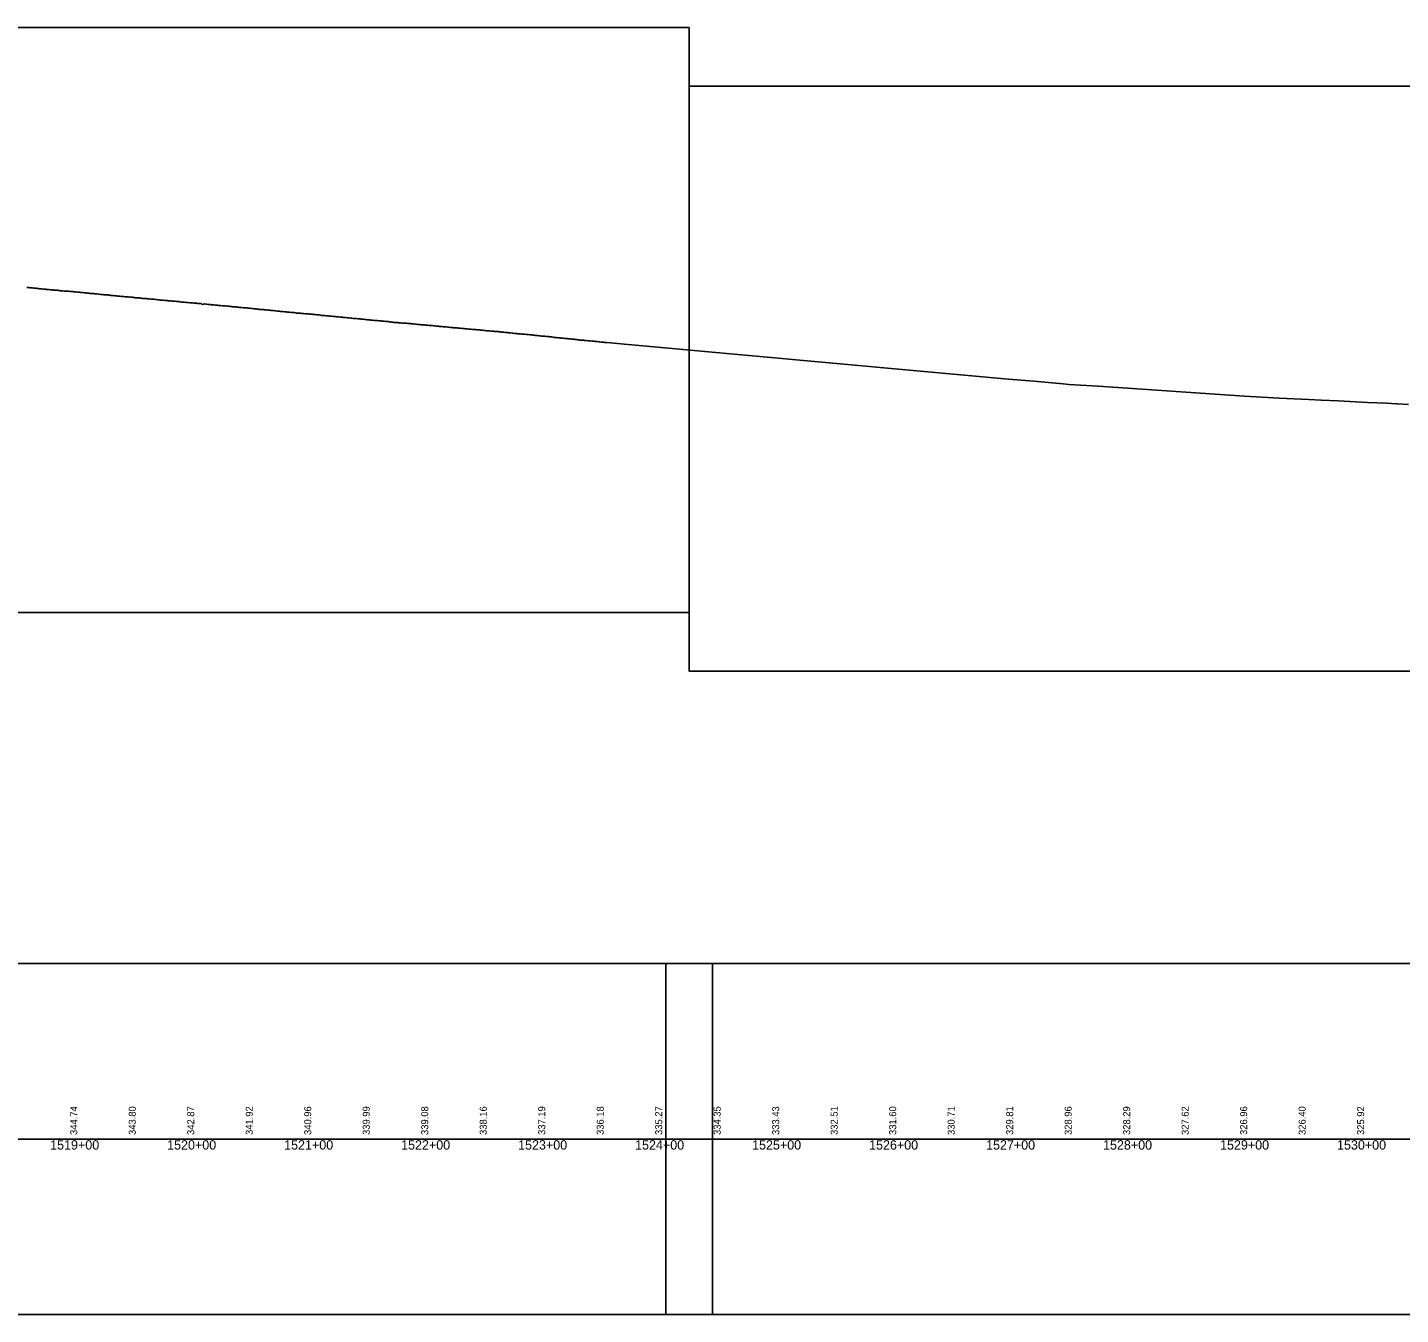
# Model space of a CAD drawing. Extents: x 2898 to 49495, y -15038 to -13538.
# Drawn here: x 41410 to 42583, y -15038 to -13938 of the extents above; entities that cross this region are included whole.
import ezdxf

# ---------------------------------------------------------------- set-up
doc = ezdxf.new("R2010")
doc.units = 0
for name, color, linetype in [('RD_DDB_Profile_EX', 7, 'Continuous'), ('RD_DDB_StaTX', 7, 'Continuous'), ('RD_DDB_StripGrade', 7, 'Continuous'), ('RD_GPK_Profile_Cell', 7, 'Continuous'), ('RD_SHT_ShtClip', 7, 'Continuous')]:
    doc.layers.add(name, color=color, linetype=linetype)

msp = doc.modelspace()

# ---------------------------------------------------------------- linework, layer by layer
at = {"layer": 'RD_DDB_Profile_EX'}
for points in [[(41409.2, -14160.7), (41410.2, -14160.8), (41411.2, -14160.8), (41412.2, -14160.9), (41413.2, -14161), (41414.2, -14161.1), (41415.2, -14161.2), (41416.2, -14161.3), (41417.2, -14161.4)], [(41417.2, -14161.4), (41418.2, -14161.6), (41419.2, -14161.7), (41420.2, -14161.8), (41421.2, -14161.9), (41422.2, -14161.9), (41423.2, -14162), (41424.2, -14162.1), (41425.2, -14162.2), (41426.2, -14162.3), (41427.2, -14162.4), (41428.2, -14162.5), (41429.2, -14162.6), (41430.2, -14162.7), (41431.2, -14162.8), (41432.2, -14162.9), (41433.2, -14163), (41434.2, -14163.1), (41435.2, -14163.1), (41436.2, -14163.3), (41437.2, -14163.4), (41438.2, -14163.5), (41439.2, -14163.5), (41440.2, -14163.6), (41441.2, -14163.7), (41442.2, -14163.7), (41443.2, -14163.8), (41444.2, -14163.9), (41445.2, -14163.9), (41446.2, -14164.1), (41447.2, -14164.1), (41448.2, -14164.2), (41449.2, -14164.3), (41450.2, -14164.5), (41451.2, -14164.5), (41452.2, -14164.7), (41453.2, -14164.8), (41454.2, -14164.8), (41455.2, -14164.9), (41456.2, -14165.1), (41457.2, -14165.1), (41458.2, -14165.2), (41459.2, -14165.3), (41460.2, -14165.4), (41461.2, -14165.5), (41462.2, -14165.6), (41463.2, -14165.7), (41464.2, -14165.8), (41465.2, -14165.9), (41466.2, -14165.9), (41467.2, -14166.1), (41468.2, -14166.1), (41469.2, -14166.2), (41470.2, -14166.4), (41471.2, -14166.5), (41472.2, -14166.6), (41473.2, -14166.7), (41474.2, -14166.8), (41475.2, -14167), (41476.2, -14166.9), (41477.2, -14167), (41478.2, -14167.1), (41479.2, -14167.2), (41480.2, -14167.3), (41481.2, -14167.4), (41482.2, -14167.5), (41483.2, -14167.6), (41484.2, -14167.7), (41485.2, -14167.7), (41486.2, -14167.8), (41487.2, -14168), (41488.2, -14168.1), (41489.2, -14168.2), (41490.2, -14168.3), (41491.2, -14168.4), (41492.2, -14168.4), (41493.2, -14168.6), (41494.2, -14168.7), (41495.2, -14168.7), (41496.2, -14168.8), (41497.2, -14168.9), (41498.2, -14169), (41499.2, -14169), (41500.2, -14169.2), (41501.2, -14169.3), (41502.2, -14169.4), (41503.2, -14169.5), (41504.2, -14169.5), (41505.2, -14169.6), (41506.2, -14169.7), (41507.2, -14169.9), (41508.2, -14170), (41509.2, -14170), (41510.2, -14170.2), (41511.2, -14170.2), (41512.2, -14170.3), (41513.2, -14170.4), (41514.2, -14170.5), (41515.2, -14170.6), (41516.2, -14170.7), (41517.2, -14170.8)], [(41517.2, -14170.8), (41518.2, -14170.8), (41519.2, -14170.9), (41520.2, -14171), (41521.2, -14171.2), (41522.2, -14171.2), (41523.2, -14171.4), (41524.2, -14171.5), (41525.2, -14171.5), (41526.2, -14171.6), (41527.2, -14171.7), (41528.2, -14171.8), (41529.2, -14171.9), (41530.2, -14172), (41531.2, -14172.1), (41532.2, -14172.2), (41533.2, -14172.3), (41534.2, -14172.4), (41535.2, -14172.4), (41536.2, -14172.5), (41537.2, -14172.6), (41538.2, -14172.8), (41539.2, -14172.8), (41540.2, -14172.9), (41541.2, -14173.1), (41542.2, -14173.1), (41543.2, -14173.2), (41544.2, -14173.3), (41545.2, -14173.4), (41546.2, -14173.6), (41547.2, -14173.6), (41548.2, -14173.7), (41549.2, -14173.8), (41550.2, -14173.8), (41551.2, -14173.9), (41552.2, -14174.1), (41553.2, -14174.1), (41554.2, -14174.2), (41555.2, -14174.3), (41556.2, -14174.4), (41557.2, -14174.5), (41558.2, -14174.5), (41559.2, -14175.3), (41560.2, -14175), (41561.2, -14174.8), (41562.2, -14174.9), (41563.2, -14175), (41564.2, -14175.1), (41565.2, -14175.2), (41566.2, -14175.3), (41567.2, -14175.4), (41568.2, -14175.5), (41569.2, -14175.6), (41570.2, -14175.7), (41571.2, -14175.8), (41572.2, -14175.9), (41573.2, -14176), (41574.2, -14176), (41575.2, -14176.2), (41576.2, -14176.3), (41577.2, -14176.3), (41578.2, -14176.4), (41579.2, -14176.5), (41580.2, -14176.6), (41581.2, -14176.7), (41582.2, -14176.8), (41583.2, -14176.9), (41584.2, -14177), (41585.2, -14177.1), (41586.2, -14177.2), (41587.2, -14177.3), (41588.2, -14177.3), (41589.2, -14177.5), (41590.2, -14177.5), (41591.2, -14177.7), (41592.2, -14177.8), (41593.2, -14177.9), (41594.2, -14178), (41595.2, -14178), (41596.2, -14178.2), (41597.2, -14178.2), (41598.2, -14178.3), (41599.2, -14178.4), (41600.2, -14178.5), (41601.2, -14178.6), (41602.2, -14178.7), (41603.2, -14178.8), (41604.2, -14178.9), (41605.2, -14179), (41606.2, -14179.1), (41607.2, -14179.2), (41608.2, -14179.4), (41609.2, -14179.5), (41610.2, -14179.6), (41611.2, -14179.6), (41612.2, -14179.7), (41613.2, -14179.9), (41614.2, -14179.9), (41615.2, -14180), (41616.2, -14180.1), (41617.2, -14180.2)], [(41617.2, -14180.2), (41618.2, -14180.3), (41619.2, -14180.4), (41620.2, -14180.5), (41621.2, -14180.6), (41622.2, -14180.7), (41623.2, -14180.8), (41624.1, -14180.9), (41625.2, -14181), (41626.2, -14181.1), (41627.1, -14181.2), (41628.2, -14181.3), (41629.2, -14181.4), (41630.2, -14181.5), (41631.2, -14181.6), (41632.1, -14181.7), (41633.2, -14181.8), (41634.2, -14181.8), (41635.1, -14182), (41636.2, -14182.1), (41637.2, -14182.1), (41638.1, -14182.2), (41639.2, -14182.4), (41640.1, -14182.5), (41641.1, -14182.5), (41642.2, -14182.6), (41643.1, -14182.7), (41644.2, -14182.8), (41645.2, -14182.9), (41646.1, -14183), (41647.2, -14183.2), (41648.1, -14183.2), (41649.1, -14183.2), (41650.2, -14183.3), (41651.1, -14183.4), (41652.1, -14183.5), (41653.1, -14183.6), (41654.1, -14183.7), (41655.2, -14183.8), (41656.1, -14183.9), (41657.1, -14184), (41658.2, -14184.1), (41659.1, -14184.2), (41660.2, -14184.3), (41661.1, -14184.5), (41662.1, -14184.6), (41663.2, -14184.6), (41664.1, -14184.7), (41665.1, -14184.8), (41666.2, -14184.9), (41667.1, -14185), (41668.1, -14185.1), (41669.1, -14185.2), (41670.1, -14185.3), (41671.2, -14185.5), (41672.1, -14185.6), (41673.1, -14185.6), (41674.2, -14185.8), (41675.1, -14185.9), (41676.1, -14185.9), (41677.1, -14186), (41678.1, -14186.1), (41679.1, -14186.2), (41680.1, -14186.3), (41681.1, -14186.4), (41682.1, -14186.4), (41683.1, -14186.5), (41684.1, -14186.6), (41685.1, -14186.7), (41686.1, -14186.8), (41687.1, -14187), (41688.1, -14187.1), (41689.1, -14187.1), (41690.1, -14187.2), (41691.1, -14187.3), (41692.1, -14187.4), (41693.1, -14187.5), (41694.1, -14187.6), (41695.1, -14187.7), (41696.1, -14187.8), (41697.1, -14187.9), (41698.1, -14188.1), (41699.1, -14188.1), (41700.1, -14188.2), (41701.1, -14188.3), (41702.1, -14188.4), (41703.1, -14188.5), (41704.1, -14188.6), (41705.1, -14188.7), (41706.1, -14188.8), (41707.1, -14188.8), (41708.1, -14188.9), (41709.1, -14189), (41710.1, -14189.1), (41711.1, -14189.2), (41712.1, -14189.3), (41713.1, -14189.4), (41714.1, -14189.5), (41715.1, -14189.6), (41716.1, -14189.7), (41717.1, -14189.8)], [(41717.1, -14189.8), (41718.1, -14189.9), (41719.1, -14190), (41720.1, -14190.1), (41721.1, -14190.2), (41722.1, -14190.2), (41723.1, -14190.5), (41724.1, -14190.5), (41725.1, -14190.5), (41726.1, -14190.6), (41727.1, -14190.8), (41728.1, -14190.9), (41729.1, -14191), (41730.1, -14191.1), (41731.1, -14191.1), (41732.1, -14191.2), (41733.1, -14191.3), (41734.1, -14191.3), (41735.1, -14191.4), (41736.1, -14191.5), (41737.1, -14191.6), (41738.1, -14191.7), (41739.1, -14191.8), (41740.1, -14191.9), (41741.1, -14192), (41742.1, -14192), (41743.1, -14192.2), (41744.1, -14192.3), (41745.1, -14192.4), (41746.1, -14192.5), (41747.1, -14192.5), (41748.1, -14192.6), (41749.1, -14192.7), (41750.1, -14192.8), (41751.1, -14192.9), (41752.1, -14193), (41753.1, -14193.1), (41754.1, -14193.1), (41755.1, -14193.2), (41756.1, -14193.3), (41757.1, -14193.5), (41758.1, -14193.6), (41759.1, -14193.7), (41760.1, -14193.7), (41761.1, -14193.8), (41762.1, -14193.9), (41763.1, -14194), (41764.1, -14194.1), (41765.1, -14194.2), (41766.1, -14194.3), (41767.1, -14194.4), (41768.1, -14194.4), (41769.1, -14194.5), (41770.1, -14194.7), (41771.1, -14194.8), (41772.1, -14194.9), (41773.1, -14195), (41774.1, -14195.1), (41775.1, -14195.2), (41776.1, -14195.2), (41777.1, -14195.3), (41778.1, -14195.4), (41779.1, -14195.4), (41780.1, -14195.6), (41781.1, -14195.7), (41782.1, -14195.7), (41783.1, -14195.8), (41784.1, -14196), (41785.1, -14196.1), (41786.1, -14196.1), (41787.1, -14196.2), (41788.1, -14196.3), (41789.1, -14196.4), (41790.1, -14196.5), (41791.1, -14196.6), (41792.1, -14196.6), (41793.1, -14196.7), (41794.1, -14196.8), (41795.1, -14196.9), (41796.1, -14197), (41797.1, -14197.1), (41798.1, -14197.1), (41799.1, -14197.2), (41800.1, -14197.4), (41801.1, -14197.5), (41802.1, -14197.6), (41803.1, -14197.7), (41804.1, -14197.7), (41805.1, -14197.8), (41806.1, -14197.9), (41807.1, -14198), (41808.1, -14198.1), (41809.1, -14198.2), (41810.1, -14198.2), (41811.1, -14198.4), (41812.1, -14198.4), (41813.1, -14198.7), (41814.1, -14198.7), (41815.1, -14198.8), (41816.1, -14198.9), (41817.1, -14199)], [(41817.1, -14199), (41818.1, -14199.1), (41819.1, -14199.2), (41820.1, -14199.3), (41821.1, -14199.4), (41822.1, -14199.4), (41823.1, -14199.5), (41824.1, -14199.7), (41825.1, -14199.8), (41826.1, -14199.9), (41827.1, -14200), (41828.1, -14200.1), (41829.1, -14200.2), (41830.1, -14200.3), (41831.1, -14200.3), (41832.1, -14200.5), (41833.1, -14200.6), (41834.1, -14200.6), (41835.1, -14200.7), (41836.1, -14200.8), (41837.1, -14200.9), (41838.1, -14200.9), (41839.1, -14201.1), (41840.1, -14201.2), (41841.1, -14201.3), (41842.1, -14201.4), (41843.1, -14201.5), (41844.1, -14201.6), (41845.1, -14201.7), (41846.1, -14201.8), (41847.1, -14201.9), (41848.1, -14202), (41849.1, -14202.2), (41850.1, -14202.2), (41851.1, -14202.3), (41852.1, -14202.4), (41853.1, -14202.5), (41854.1, -14202.6), (41855.1, -14202.7), (41856.1, -14202.8), (41857.1, -14202.9), (41858.1, -14203), (41859.1, -14203.2), (41860.1, -14203.3), (41861.1, -14203.4), (41862.1, -14203.5), (41863.1, -14203.6), (41864.1, -14203.7), (41865.1, -14203.8), (41866.1, -14203.9), (41867.1, -14204), (41868.1, -14204.1), (41869.1, -14204.2), (41870.1, -14204.3), (41871.1, -14204.4), (41872.1, -14204.5), (41873.1, -14204.6), (41874.1, -14204.7), (41875.1, -14204.9), (41876.1, -14204.9), (41877.1, -14205), (41878.1, -14205.1), (41879.1, -14205.2), (41880.1, -14205.3), (41881.1, -14205.4), (41882.1, -14205.6), (41883.1, -14205.7), (41884.1, -14205.7), (41885.1, -14205.8), (41886.1, -14205.9), (41887.1, -14206), (41888.1, -14206.1), (41889.1, -14206.2), (41890.1, -14206.4), (41891.1, -14206.4), (41892.1, -14206.5), (41893.1, -14206.6), (41894.1, -14206.7), (41895.1, -14206.8), (41896.1, -14206.9), (41897.1, -14206.9), (41898.1, -14207.1), (41899.1, -14207.2), (41900.1, -14207.3), (41901.1, -14207.4), (41902.1, -14207.5), (41903.1, -14207.6), (41904.1, -14207.6), (41905.1, -14207.7), (41920.2, -14209.1), (41945.2, -14211.4), (41970.2, -14213.7), (41995.2, -14216), (42020.1, -14218.3), (42045.1, -14220.6), (42070.1, -14222.9), (42095.1, -14225.2), (42120.1, -14227.5), (42145.1, -14229.7), (42170.1, -14231.9), (42195.1, -14234.2)], [(42195.1, -14234.2), (42220.1, -14236.4), (42245.1, -14238.7), (42270.1, -14240.9), (42295, -14243.1), (42300, -14243.5), (42325, -14245.1), (42350.1, -14246.8), (42375.1, -14248.5), (42400.1, -14250.1), (42425.1, -14251.8), (42450.1, -14253.5), (42474.9, -14255.1), (42480.1, -14255.4), (42505, -14256.5), (42515.7, -14257.1), (42530.1, -14257.7), (42555.2, -14258.9), (42571.4, -14259.7), (42580, -14260.1), (42580.3, -14260.1), (42580.8, -14260.2), (42590.3, -14260.6)]]:
    msp.add_lwpolyline(points, dxfattribs=at)
at = {"layer": 'RD_GPK_Profile_Cell'}
msp.add_line((2976.1, -14888.5), (48721.1, -14888.5), dxfattribs=at)
at = {"layer": 'RD_SHT_ShtClip'}
for points in [[(40475.4, -13938.5), (40475.4, -14438.5), (41975.4, -14438.5), (41975.4, -14438.5), (41975.4, -13938.5), (41975.4, -13938.5)], [(41975.4, -13988.5), (41975.4, -14488.5), (43475.4, -14488.5), (43475.4, -14488.5), (43475.4, -13988.5), (43475.4, -13988.5)], [(40455.4, -14738.5), (41995.4, -14738.5), (41995.4, -15038.5), (40455.4, -15038.5)], [(41955.4, -14738.5), (43495.4, -14738.5), (43495.4, -15038.5), (41955.4, -15038.5)]]:
    msp.add_lwpolyline(points, close=True, dxfattribs=at)

# ---------------------------------------------------------------- texts
at = {"layer": 'RD_DDB_StaTX'}
for s, p in [('1519+00', (41429.2, -14897.5)), ('1520+00', (41529.2, -14897.5)), ('1521+00', (41629.2, -14897.5)), ('1522+00', (41729.2, -14897.5)), ('1523+00', (41829.2, -14897.5)), ('1524+00', (41929.2, -14897.5)), ('1525+00', (42029.2, -14897.5)), ('1526+00', (42129.2, -14897.5)), ('1527+00', (42229.2, -14897.5)), ('1528+00', (42329.2, -14897.5)), ('1529+00', (42429.2, -14897.5)), ('1530+00', (42529.2, -14897.5))]:
    msp.add_text(s, height=8, dxfattribs=at).set_placement(p)
at = {"layer": 'RD_DDB_StripGrade'}
for s, p in [('344.74', (41452.4, -14885)), ('343.80', (41502.4, -14885)), ('342.87', (41552.4, -14885)), ('341.92', (41602.4, -14885)), ('340.96', (41652.4, -14885)), ('339.99', (41702.4, -14885)), ('339.08', (41752.4, -14885)), ('338.16', (41802.4, -14885)), ('337.19', (41852.4, -14885)), ('336.18', (41902.4, -14885)), ('335.27', (41952.4, -14885)), ('334.35', (42002.4, -14885)), ('333.43', (42052.4, -14885)), ('332.51', (42102.4, -14885)), ('331.60', (42152.4, -14885)), ('330.71', (42202.4, -14885)), ('329.81', (42252.4, -14885)), ('328.96', (42302.4, -14885)), ('328.29', (42352.4, -14885)), ('327.62', (42402.4, -14885)), ('326.96', (42452.4, -14885)), ('326.40', (42502.4, -14885)), ('325.92', (42552.4, -14885))]:
    msp.add_text(s, height=6, rotation=90, dxfattribs=at).set_placement(p)

doc.saveas('drawing.dxf')
